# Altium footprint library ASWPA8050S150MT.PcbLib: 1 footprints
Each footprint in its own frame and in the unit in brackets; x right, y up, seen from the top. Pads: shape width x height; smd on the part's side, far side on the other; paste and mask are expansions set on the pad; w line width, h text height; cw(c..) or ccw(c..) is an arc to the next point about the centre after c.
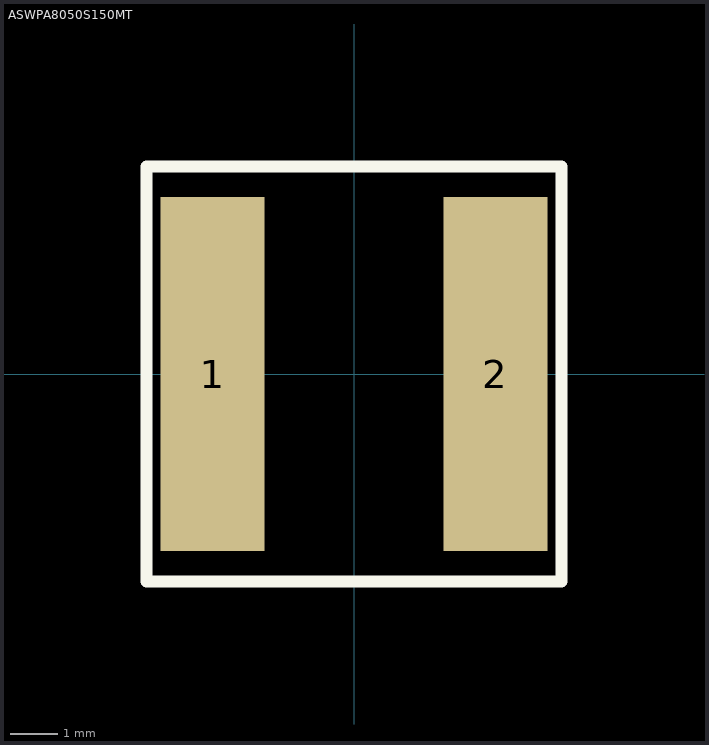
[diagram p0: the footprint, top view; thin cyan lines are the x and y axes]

## ASWPA8050S150MT [mm]
height 5
pads (2):
  rect 2.2x7.5 smd: 1(-3,0) 2(3,0)
Top Overlay:
  lines w0.254: -4.4,-4.4 4.4,-4.4 4.4,4.4 -4.4,4.4 -4.4,-4.4
M5 Assembly Top:
  text ".Designator" at -1.8,-0.514 h1.02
